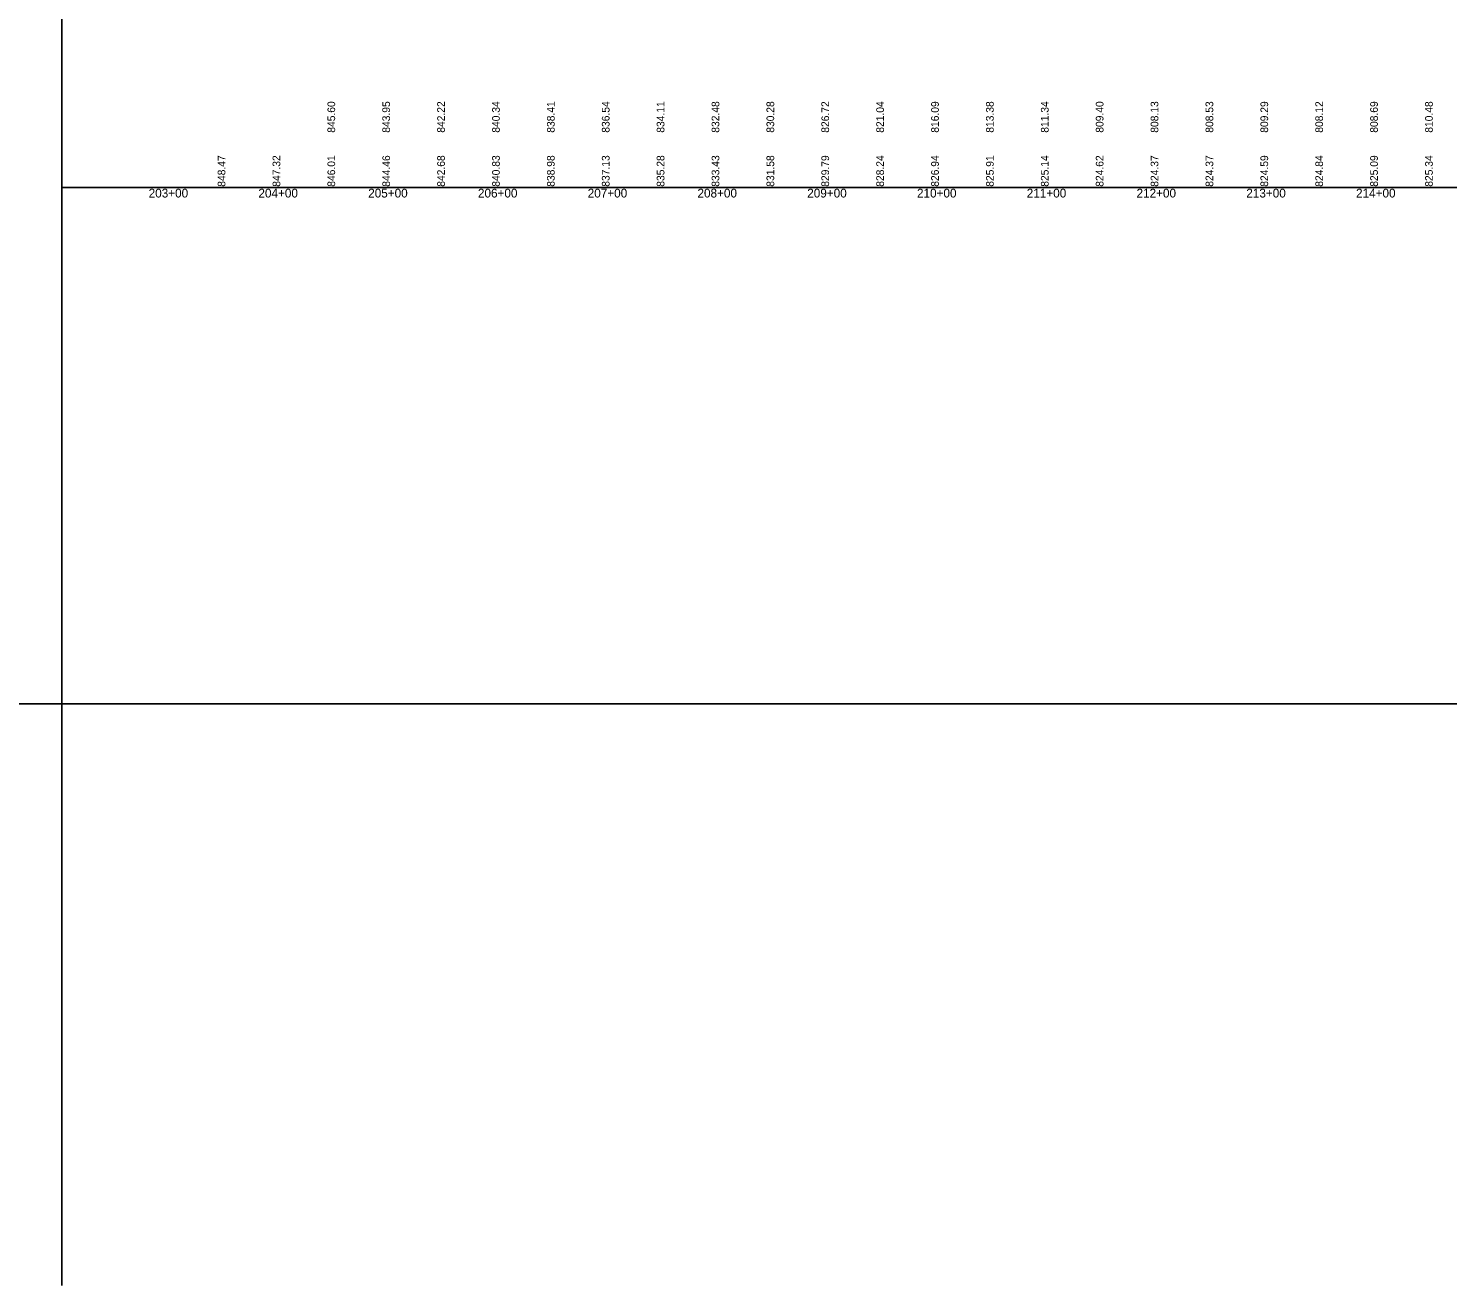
# Model space of a CAD drawing. Extents: x 1475855 to 1480900, y 1104511 to 1111511.
# Drawn here: x 1477333 to 1478626, y 1104511 to 1105656 of the extents above; entities that cross this region are included whole.
import ezdxf

# ---------------------------------------------------------------- set-up
doc = ezdxf.new("R2010")
doc.units = 0
for name, color, linetype in [('RD_DDB_StaTX', 7, 'Continuous'), ('RD_DDB_StripGrade', 7, 'Continuous'), ('RD_GPK_Profile_Cell', 7, 'Continuous'), ('RD_Sketch7', 7, 'Continuous')]:
    doc.layers.add(name, color=color, linetype=linetype)

msp = doc.modelspace()

# ---------------------------------------------------------------- linework, layer by layer
at = {"layer": 'RD_GPK_Profile_Cell'}
for q in [(1477363.5, 1106511.2), (1479982.4, 1105511.2), (1477363.5, 1104511.2)]:
    msp.add_line((1477363.5, 1105511.2), q, dxfattribs=at)
at = {"layer": 'RD_Sketch7'}
msp.add_lwpolyline([(1477173.9, 1105041.2), (1480053.9, 1105041.2), (1480053.9, 1106801.2), (1477173.9, 1106801.2)], close=True, dxfattribs=at)

# ---------------------------------------------------------------- texts
at = {"layer": 'RD_DDB_StaTX'}
for s, p in [('203+00', (1477442.6, 1105502.2)), ('204+00', (1477542.6, 1105502.2)), ('205+00', (1477642.6, 1105502.2)), ('206+00', (1477742.6, 1105502.2)), ('207+00', (1477842.6, 1105502.2)), ('208+00', (1477942.6, 1105502.2)), ('209+00', (1478042.6, 1105502.2)), ('210+00', (1478142.6, 1105502.2)), ('211+00', (1478242.6, 1105502.2)), ('212+00', (1478342.6, 1105502.2)), ('213+00', (1478442.6, 1105502.2)), ('214+00', (1478542.6, 1105502.2))]:
    msp.add_text(s, height=8, dxfattribs=at).set_placement(p)
at = {"layer": 'RD_DDB_StripGrade'}
for s, p in [('845.60', (1477612.5, 1105561.2)), ('843.95', (1477662.5, 1105561.2)), ('842.22', (1477712.5, 1105561.2)), ('840.34', (1477762.5, 1105561.2)), ('838.41', (1477812.5, 1105561.2)), ('836.54', (1477862.5, 1105561.2)), ('834.11', (1477912.5, 1105561.2)), ('832.48', (1477962.5, 1105561.2)), ('830.28', (1478012.5, 1105561.2)), ('826.72', (1478062.5, 1105561.2)), ('821.04', (1478112.5, 1105561.2)), ('816.09', (1478162.5, 1105561.2)), ('813.38', (1478212.5, 1105561.2)), ('811.34', (1478262.5, 1105561.2)), ('809.40', (1478312.5, 1105561.2)), ('808.13', (1478362.5, 1105561.2)), ('808.53', (1478412.5, 1105561.2)), ('809.29', (1478462.5, 1105561.2)), ('808.12', (1478512.5, 1105561.2)), ('808.69', (1478562.5, 1105561.2)), ('810.48', (1478612.5, 1105561.2)), ('848.47', (1477512.5, 1105512)), ('847.32', (1477562.5, 1105512)), ('846.01', (1477612.5, 1105512)), ('844.46', (1477662.5, 1105512)), ('842.68', (1477712.5, 1105512)), ('840.83', (1477762.5, 1105512)), ('838.98', (1477812.5, 1105512)), ('837.13', (1477862.5, 1105512)), ('835.28', (1477912.5, 1105512)), ('833.43', (1477962.5, 1105512)), ('831.58', (1478012.5, 1105512)), ('829.79', (1478062.5, 1105512)), ('828.24', (1478112.5, 1105512)), ('826.94', (1478162.5, 1105512)), ('825.91', (1478212.5, 1105512)), ('825.14', (1478262.5, 1105512)), ('824.62', (1478312.5, 1105512)), ('824.37', (1478362.5, 1105512)), ('824.37', (1478412.5, 1105512)), ('824.59', (1478462.5, 1105512)), ('824.84', (1478512.5, 1105512)), ('825.09', (1478562.5, 1105512)), ('825.34', (1478612.5, 1105512))]:
    msp.add_text(s, height=7, rotation=90, dxfattribs=at).set_placement(p)
at = {"layer": 'RD_GPK_Profile_Cell'}
for s in ['001', 'ALT1', '20200.000000', '750', '10', '2', 'NOGAP']:
    msp.add_text(s, height=0.00975, dxfattribs=at).set_placement((1477363.5, 1105511.3))

doc.saveas('drawing.dxf')
